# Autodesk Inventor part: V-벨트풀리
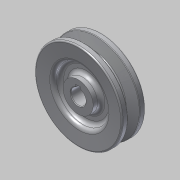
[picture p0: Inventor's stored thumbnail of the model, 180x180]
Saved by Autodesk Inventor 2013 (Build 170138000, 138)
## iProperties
Created: 2016-08
Part Number: V-벨트풀리
Material: 알루미늄 6061
Document SubType Name: Modeling
Designer: mduedu
Density: 2.71 g/cm^3
Author: mduedu
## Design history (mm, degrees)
sketch "스케치1"
  geometry: L1 (0, 9.5)-(0, -9.5); L2 (0, 9.5)-(35, 9.5); L3 (35, 9.5)-(35, 4.825); L4 (35, 4.825)-(26, 2.074); L5 (26, 2.074)-(26, 0); L6 (0, 0)-(26, 0); L7 (0, -9.5)-(35, -9.5); L8 (35, -9.5)-(35, -4.825); L9 (35, -4.825)-(26, -2.074); L10 (26, -2.074)-(26, 0); L11 (32.3, 9.5)-(32.3, -9.5); 3 further points
  constraints: 22 end point, 6 point on line, 4 perpendicular, 3 symmetric about line, 1 coincident, 1 horizontal alignment, 1 midpoint, 1 parallel, 1 vertical
  dimensions: "d0" = 19 distance of L1.start L1.end; "d2" = 70 diameter of L8 L1; "d4" = 6.3 distance between parallel lines of L10 L11; "d5" = 2.7 distance between parallel lines of L11 L8; "d6" = 8 distance of point (32.3, -4) point (32.3, 4); "d7" = 34 deg angle of L9 L4
revolve "회전1" sketch "스케치1" stored, may be unused: angle "d8" = 90 deg
sketch "스케치2"
  geometry: L1 (-2, 0)-(2, 0); L2 (2, 0)-(2, 7.8); L3 (2, 7.8)-(-2, 7.8); L4 (-2, 7.8)-(-2, 0); C1 r 6 at (0, 0); 2 further points
  constraints: 8 end point, 2 coincident, 2 parallel, 1 centre point, 1 horizontal, 1 midpoint, 1 perpendicular
  dimensions: "d9" = 12 diameter of C1; "d11" = 4 distance of L2.end L3.end; "d12" = 7.8 distance of L1.end L2.end
extrude "돌출1" cut sketch "스케치2" stored distance "d13" = 10; taper "d14" = 0 deg
sketch "스케치3"
  geometry: L1 (35, 4.825)-(26, 2.074) reference; L2 (26, 2.074)-(26, -2.074) reference; L3 (0, 0)-(26, 0); L4 (35, 9.5)-(35, 4.825) reference; L5 (-35, 9.5)-(35, 9.5) reference; L6 (35, 9.5)-(21, 8.275); L7 (21, 8.275)-(21, 3); L8 (21, 3)-(12, 3); L9 (12, 3)-(12, 9.5); L10 (0, 9.5)-(0, -9.5); L11 (5.657, -9.5)-(-6, -9.5) reference; L12 (12, 9.5)-(35, 9.5)
  constraints: 14 end point, 3 midpoint, 2 perpendicular, 2 point on line, 1 collinear, 1 horizontal, 1 parallel
  dimensions: "d15" = 3 distance between parallel lines of L3 L8; "d17" = 42 diameter of L7 L10; "d18" = 24 diameter of L9 L10; "d31" = 5 deg angle of L6 L5
revolve "회전2" sketch "스케치3" stored, may be unused: angle "d19" = 90 deg
fillet "모깎기1" dims "d20" = 0.5, "d21" = 1, "d22" = 1
fillet "모깎기2" dims "d23" = 3
fillet "모깎기3" dims "d24" = 3
fillet "모깎기4" dims "d25" = 3
chamfer "모따기1" distance "d26" = 0.5; stored, may be unused: second distance "d27" = 2, angle "d28" = 45 deg
node "솔리드1"
mirror "대칭1"
